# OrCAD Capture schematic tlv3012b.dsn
size A
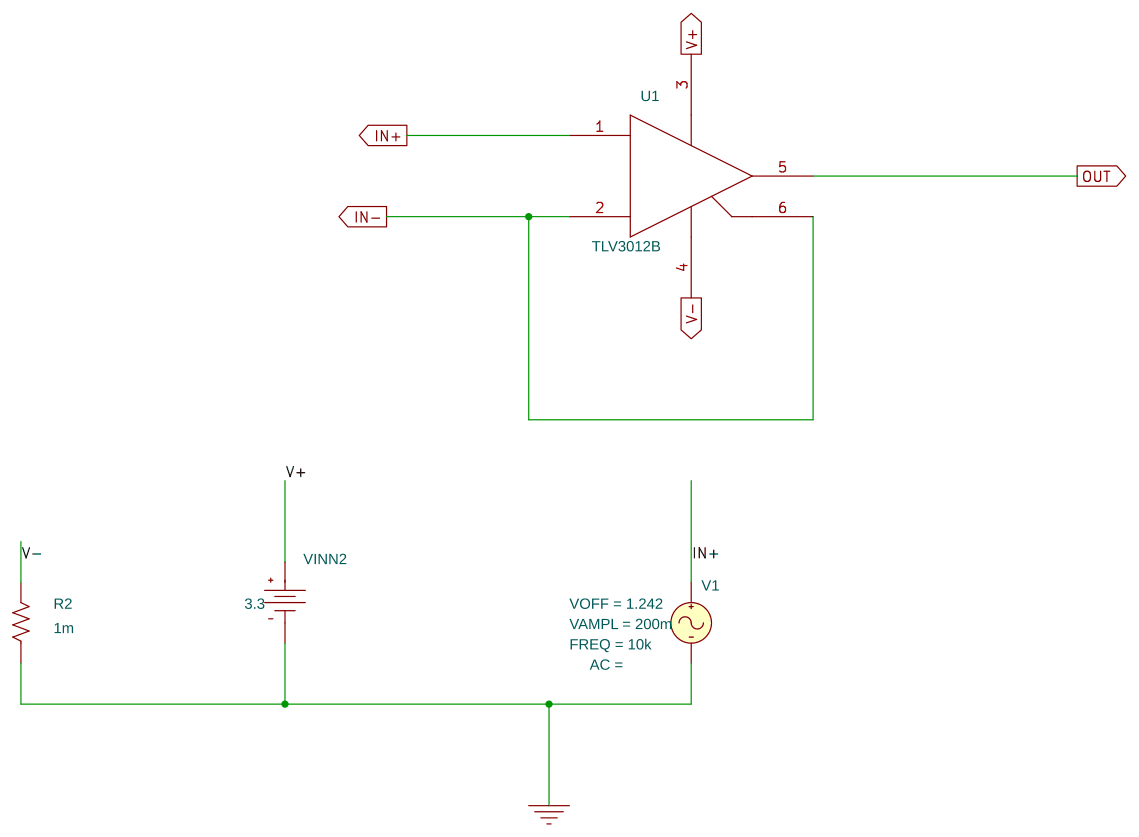
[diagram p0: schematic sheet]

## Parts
R2  1m  [AXRC05]
U1  TLV3012B
V1  VSIN
VINN2  VDC

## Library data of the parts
R2 = R
U1 = TLV3012B
V1 = VSIN: FREQ: 10k; VAMPL: 200m; VOFF: 1.242
VINN2 = VDC: DC: 3.3

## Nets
0: R2.1 V1.2(-) VINN2.1(-)
IN+: U1.1(IN+) V1.1(+)
IN-: U1.2(IN-) U1.6(REF)
OUT: U1.5(OUT)
V+: U1.3(V+) VINN2.0(+)
V-: R2.2 U1.4(V-)
